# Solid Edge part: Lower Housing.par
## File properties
Author: CADCIM
Template: NORMENG.PAR
Last saved by: Cadcim
Revision: 6
Application: Solid Edge
Accuracy: 0.99
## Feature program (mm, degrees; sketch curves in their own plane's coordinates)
sketch for "unnamed Protrusion 1" plane through (0, 0, 0) normal (0, -1, 0) x-axis (1, 0, 0)
  line (0, 0) -> (-190.5, 0)
  line (-190.5, 0) -> (-190.5, -10.414)
  line (-190.5, -10.414) -> (-152.4, -10.414)
  arc centre (-0.1761, -3.0894) radius 152.4 from (-88.9, -127) to (-152.4, -10.414) cw
  line (-88.9, -127) -> (-177.8, -127)
  line (-177.8, -127) -> (-177.8, -165.1)
  line (-177.8, -165.1) -> (0, -165.1)
  line (177.8, -165.1) -> (0, -165.1)
  line (177.8, -127) -> (177.8, -165.1)
  line (88.9, -127) -> (177.8, -127)
  arc centre (0.1761, -3.0894) radius 152.4 from (88.9, -127) to (152.4, -10.414) ccw
  line (190.5, -10.414) -> (152.4, -10.414)
  line (190.5, 0) -> (190.5, -10.414)
  line (0, 0) -> (190.5, 0)
extrude "unnamed Protrusion 1" add finite 203.2 symmetric
sketch for "RevolvedCutout_1" plane through (0, 0, 0) normal (0, 0, 1) x-axis (0, 1, 0)
  line (-95.25, 0) -> (95.25, 0)
  line (95.25, 0) -> (95.25, 146.05)
  line (95.25, 146.05) -> (-95.25, 146.05)
  line (-95.25, 146.05) -> (-95.25, 0)
  dimension (linear) = 95.25
revolve "RevolvedCutout_1" cut finite 180 deg
sketch for "unnamed Cutout 1" plane through (0, -101.6, -82.55) normal (0, -1, 0) x-axis (1, 0, 0)
  arc centre (0, 82.55) radius 123.825 from (123.825, 82.55) to (-123.825, 82.55) cw
  line (-123.825, 82.55) -> (123.825, 82.55)
extrude "unnamed Cutout 1" cut through along -normal
sketch for "unnamed Cutout 2" plane through (0, 101.6, -82.55) normal (0, 1, 0) x-axis (-1, 0, 0)
  arc centre (0, 82.55) radius 38.1 from (38.1, 82.55) to (-38.1, 82.55) cw
  line (-38.1, 82.55) -> (38.1, 82.55)
extrude "unnamed Cutout 2" cut through along -normal
sketch for "Hole_1" plane through (114.3, 0, 0) normal (0, 0, 1) x-axis (0, 1, 0)
  hole centre (-76.2, -57.15) bore radius 5.207
hole "Hole_1" diameter 10.414 through
pattern "unnamed Pattern 1" of "Hole_1"
pattern "unnamed Pattern 2"
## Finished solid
Body 1: solid body, 28 faces, 70 edges, 36 vertices.
  Faces by surface: plane 15, cylinder 13
  Edges by curve: line 44, circle 26
Bounding box of the edges (mm): 381.000 x 203.200 x 165.100, from (-190.5, -101.6, -165.1) to (190.5, 101.6, 0).
Cylindrical faces by radius (mm): R5.207 x8, R38.1 x1, R123.825 x1, R146.05 x1, R152.4 x2
Planar faces by outward normal: +x 2, +y 2, +z 4, -x 2, -y 2, -z 3
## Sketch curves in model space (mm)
line (190.5, 0, 0) -> (190.5, 0, -10.414)
line (190.5, 0, -10.414) -> (152.4, 0, -10.414)
arc centre (0.1761, 0, -3.0894) radius 152.4 from (88.9, 0, -127) through (134.012, 0, -75.9848) to (152.4, 0, -10.414)
line (88.9, 0, -127) -> (177.8, 0, -127)
line (177.8, 0, -127) -> (177.8, 0, -165.1)
line (177.8, 0, -165.1) -> (0, 0, -165.1)
line (-177.8, 0, -165.1) -> (0, 0, -165.1)
line (-177.8, 0, -127) -> (-177.8, 0, -165.1)
line (-88.9, 0, -127) -> (-177.8, 0, -127)
arc centre (-0.1761, 0, -3.0894) radius 152.4 from (-88.9, 0, -127) through (-134.012, 0, -75.9848) to (-152.4, 0, -10.414)
line (-190.5, 0, -10.414) -> (-152.4, 0, -10.414)
line (-190.5, 0, 0) -> (-190.5, 0, -10.414)
line (0, 0, 0) -> (-190.5, 0, 0)
line (0, 0, 0) -> (190.5, 0, 0)
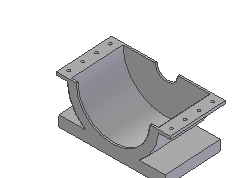
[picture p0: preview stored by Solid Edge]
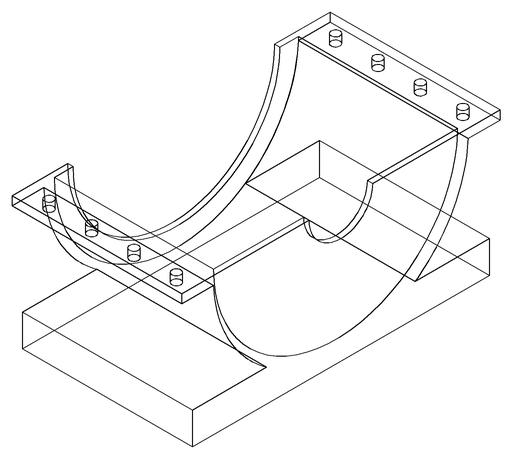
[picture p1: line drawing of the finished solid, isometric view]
